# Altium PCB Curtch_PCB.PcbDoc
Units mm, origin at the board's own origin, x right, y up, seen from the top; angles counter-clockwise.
Board outline 152.4 x 101.6 mm, 2 copper layers (Top Layer, Bottom Layer); 8 components, 15 nets, 77 pads, 8 vias.
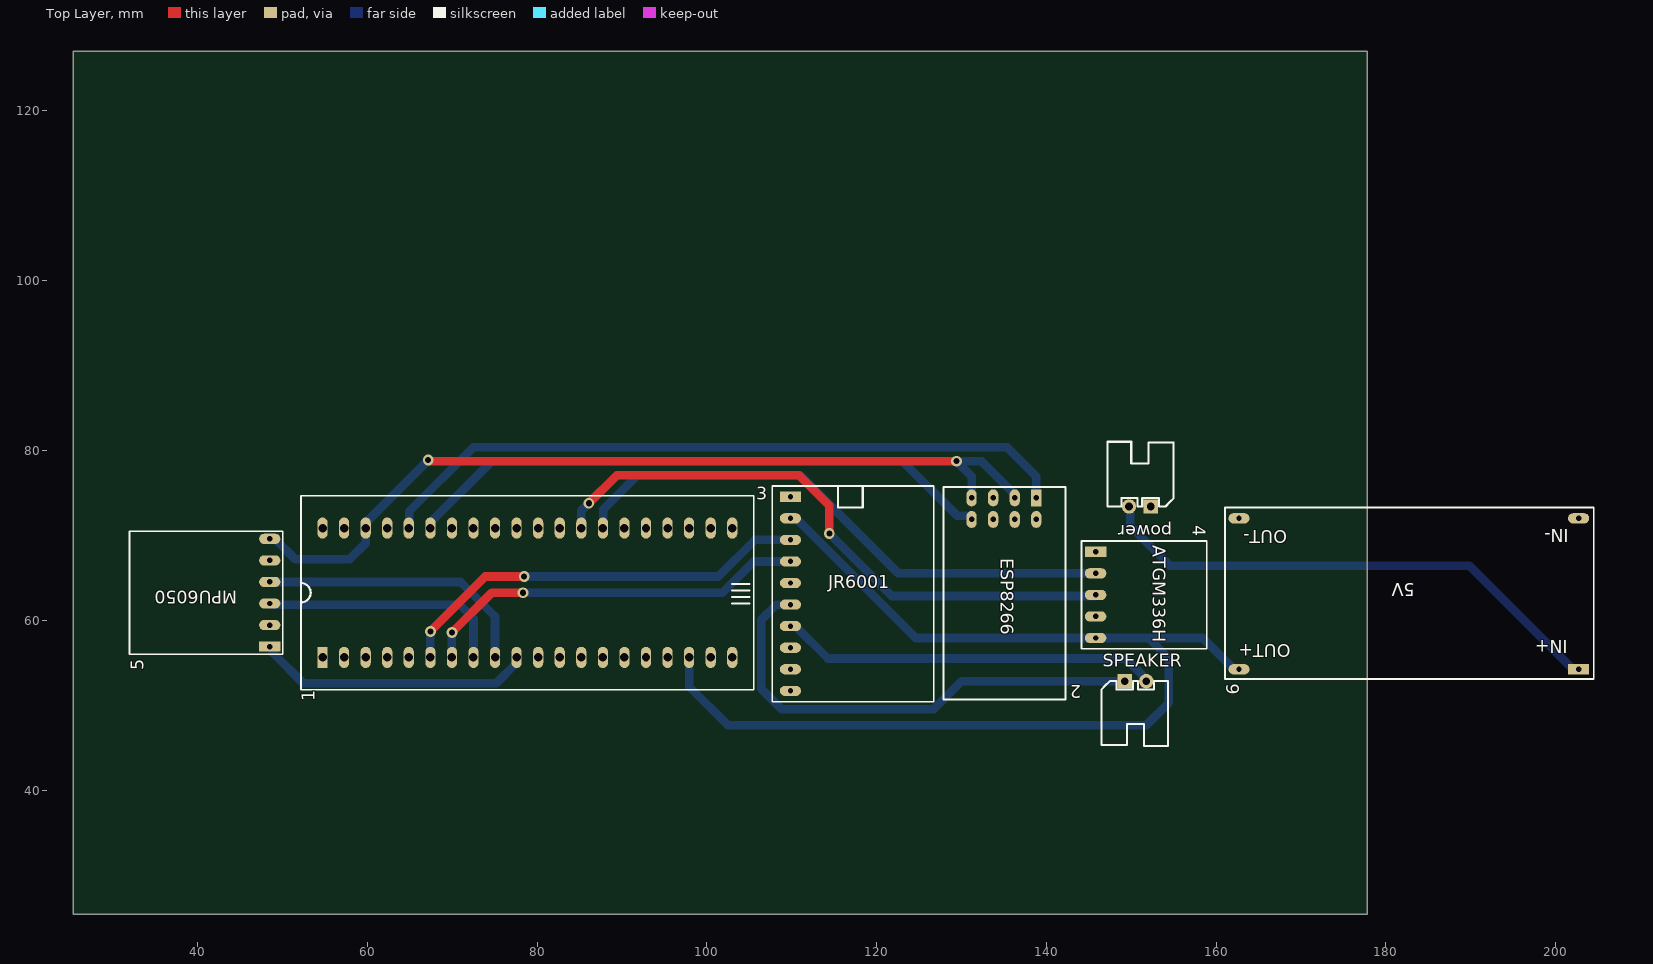
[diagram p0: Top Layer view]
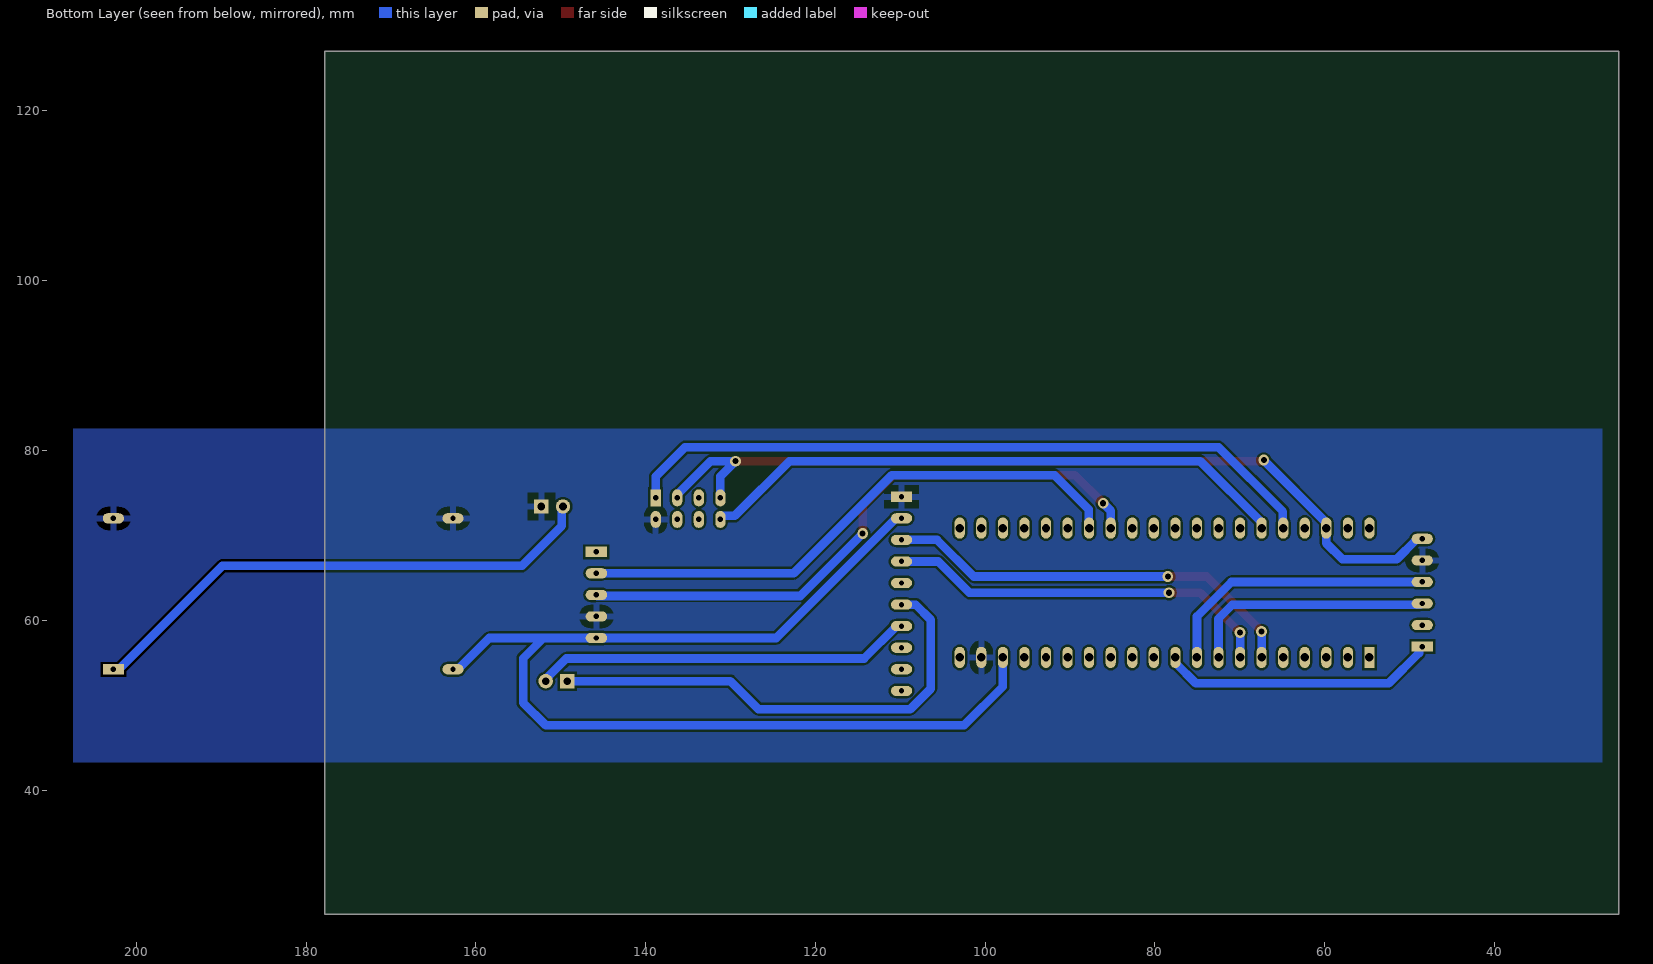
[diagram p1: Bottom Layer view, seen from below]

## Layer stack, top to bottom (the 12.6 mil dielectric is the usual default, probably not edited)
Top Solder: solder mask 0.0102, Solder Resist, Dk 3.5
Top Layer: signal copper 0.0356
Dielectric 1: dielectric 0.32, FR-4, Dk 4.8
Bottom Layer: signal copper 0.0356
Bottom Solder: solder mask 0.0102, Solder Resist, Dk 3.5

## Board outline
25.4,25.4 177.8,25.4 177.8,127 25.4,127

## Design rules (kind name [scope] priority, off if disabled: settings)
Clearance [All] p1: gap=0.254 ignorepadtopadclearanceinfootprint=FALSE except(0: Arc-Hole Track-Hole SMDPad-Hole THPad-Hole Via-Hole Fill-Hole Poly-Hole Region-Hole Text-Hole)
PlaneClearance [InNet('GND')] p1: clearance=0.508
PlaneConnect PlaneConnect_1 [All] p1: planeconnectstyle=Relief reliefexpansion=0.508 reliefentries=4 reliefconductorwidth=0.254 reliefairgap=0.254
PolygonConnect [InNet('GND') vs InNet('GND')] p1: connectstyle=Relief reliefconductorwidth=0.762 reliefentries=4 polygonreliefangle="90 Angle" airgapwidth=0.762
RoutingVias [All] p1: holewidth=0.711 width=1.27 viastyle="Through Hole" minholewidth=0.711 minwidth=1.27 maxholewidth=0.711 maxwidth=1.27
SolderMaskExpansion [All] p1: expansion=0.102 istentingtop=FALSE
Width [All] p1: maxlimit=1.016 minlimit=0.762 preferedwidth=1.016
28 further rules are at their usual default settings.

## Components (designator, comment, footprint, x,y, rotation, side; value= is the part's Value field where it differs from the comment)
1 "STM32最小系统板" DIP40 54.737,55.626 r90 top
2 "ESP8266" "DIP8 - duplicate" 138.811,74.422 r270 top
3 "JR6001" DIP20 109.855,74.549 r0 top
4 "ATGM336H" DIP10 145.796,68.072 r0 top
5 "MPU6050" MPU6050 48.514,56.896 r180 top
6 "5V稳压" DIP16 202.687,54.229 r180 top
power "HDR-1X2" XH2.54-WI-2P 151.003,73.406 r180 top
SPEAKER "HDR-1X2" XH2.54-WI-2P 150.495,52.832 r0 top

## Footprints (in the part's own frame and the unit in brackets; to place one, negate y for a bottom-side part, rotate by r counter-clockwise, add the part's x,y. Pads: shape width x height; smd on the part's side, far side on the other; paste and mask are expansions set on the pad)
"DIP8 - duplicate" [mm]
  rect 2x1.2 hole 0.64: 1(0,0)
  oval 2x1.2 hole 0.64: 2(0,-2.54) 3(0,-5.08) 4(0,-7.62) 5(2.54,-7.62) 6(2.54,-5.08) 7(2.54,-2.54) 8(2.54,0)
  silkscreen extent -1.27,-10.92 23.75,3.43
DIP10 [mm]
  rect 2.54x1.2 / inner rect 2.5x1.2 / far side rect 2.54x1.2 hole 0.64: 1(0,0)
  oval 2.54x1.2 / inner oval 2.5x1.2 / far side oval 2.54x1.2 hole 0.64: 2(0,-2.54) 3(0,-5.08) 4(0,-7.62) 5(0,-10.16)
  silkscreen extent -1.65,-11.43 13.1,1.27
DIP16 [mm]
  rect 2.5x1.2 hole 0.64: 1(0,0)
  oval 2.5x1.2 hole 0.64: 2(0,-17.78) 3(40,-17.78) 4(40,0)
  silkscreen extent -1.78,-19.05 41.66,1.14
DIP20 [mm]
  rect 2.5x1.2 hole 0.64: 1(0,0)
  oval 2.5x1.2 hole 0.64: 2(0,-2.54) 3(0,-5.08) 4(0,-7.62) 5(0,-10.16) 6(0,-12.7) 7(0,-15.24) 8(0,-17.78) 9(0,-20.32) 10(0,-22.86)
  silkscreen extent -2.16,-24.13 16.89,1.27
DIP40 [mm]
  rect 2.5x1.2 hole 1: 1(0,0)
  oval 2.5x1.2 hole 1: 2(0,-2.54) 3(0,-5.08) 4(0,-7.62) 5(0,-10.16) 6(0,-12.7) 7(0,-15.24) 8(0,-17.78) 9(0,-20.32) 10(0,-22.86) 11(0,-25.4) 12(0,-27.94) 13(0,-30.48) 14(0,-33.02) 15(0,-35.56) 16(0,-38.1) 17(0,-40.64) 18(0,-43.18) 19(0,-45.72) 20(0,-48.26) 21(15.24,-48.26) 22(15.24,-45.72) 23(15.24,-43.18) 24(15.24,-40.64) 25(15.24,-38.1) 26(15.24,-35.56) 27(15.24,-33.02) 28(15.24,-30.48) 29(15.24,-27.94) 30(15.24,-25.4) 31(15.24,-22.86) 32(15.24,-20.32) 33(15.24,-17.78) 34(15.24,-15.24) 35(15.24,-12.7) 36(15.24,-10.16) 37(15.24,-7.62) 38(15.24,-5.08) 39(15.24,-2.54) 40(15.24,0)
  silkscreen extent -3.81,-50.8 19.05,2.54
MPU6050 [mm]
  rect 2.5x1.2 hole 0.64: 1(0,0)
  oval 2.5x1.2 hole 0.64: 2(0,-2.54) 3(0,-5.08) 4(0,-7.62) 5(0,-10.16) 6(0,-12.7)
  silkscreen extent -1.52,-13.59 16.51,0.89
XH2.54-WI-2P [mm] "接插件，2P"
  rect 1.7x1.7 hole 0.9: 1(-1.27,0)
  round 1.7 hole 0.9: 2(1.27,0)
  silkscreen extent -3.99,-7.62 3.81,0, body extent -3.77,-7.35 3.77,0.35, height 5.73

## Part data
2: library part Component_1
power SPEAKER: library part "Header 2", "2P接插件"

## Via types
v1: diameter 1.27, hole 0.711, Top Layer to Bottom Layer, 8 vias

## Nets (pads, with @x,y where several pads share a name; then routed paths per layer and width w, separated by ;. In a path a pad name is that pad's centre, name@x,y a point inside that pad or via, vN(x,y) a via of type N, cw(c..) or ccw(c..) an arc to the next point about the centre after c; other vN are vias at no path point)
3.3V: 1.38 2.2 2.4 5.6 | length 102
  Top Layer w1.016: v1(67.183,78.867) 67.252,78.867 67.379,78.74 v1(129.413,78.74)
  Bottom Layer w1.016: 5.6 49.114,69.596 49.256,69.454 49.256,69.449 51.522,67.183 57.912,67.183 59.817,69.088 1.38 59.817,71.501 v1@67.056,78.74 ; 2.4 131.191,76.962 v1(129.413,78.74) 132.353,78.74 136.271,74.822 2.2
5V: 1.18 3.2 4.5 6.4 | length 131.9
  Top Layer w1.016: 3.2 3.2@109.982,71.882
  Bottom Layer w1.016: 1.18 97.917,52.197 102.489,47.625 151.765,47.625 154.432,50.292 154.432,55.499 152.019,57.912 ; 3.2 110.505,72.009 124.602,57.912 4.5 152.019,57.912 ; 6.4 162.087,54.229 158.404,57.912 152.019,57.912
8V: 6.1 power.2 | length 62.2
  Bottom Layer w1.016: power.2 149.864,73.275 149.864,71.116 154.559,66.421 189.845,66.421 202.037,54.229 6.1
GND: 1.19 2.8 3.1 4.4 5.5 6.2 6.3 power.1
PA2: 1.27 4.2 | length 66.7
  Bottom Layer w1.016: 1.27 87.792,70.901 87.792,73.06 91.821,77.089 110.998,77.089 122.555,65.532 4.2
PA3: 1.28 4.3 | length 72.2
  Top Layer w1.016: v1(86.106,73.787) 89.408,77.089 110.871,77.089 114.427,73.533 v1(114.427,70.231)
  Bottom Layer w1.016: 1.28 85.217,72.898 v1(86.106,73.787) ; v1(114.427,70.231) 121.793,62.865 145.669,62.865 4.3
PA9: 1.6 3.3 | length 49.9
  Top Layer w1.016: v1(67.437,58.674) 73.914,65.151 v1(78.486,65.151)
  Bottom Layer w1.016: 1.6 v1(67.437,58.674) ; v1(78.486,65.151) 101.346,65.151 105.664,69.469 3.3
PA10: 1.7 3.4 | length 46.3
  Top Layer w1.016: v1(69.977,58.547) 74.676,63.246 v1(78.333,63.246)
  Bottom Layer w1.016: 1.7 v1(69.977,58.547) ; v1(78.333,63.246) 101.854,63.246 105.537,66.929 3.4
PA11: 1.8 5.3 | length 29.3
  Bottom Layer w1.016: 5.3 48.641,61.976 48.768,61.849 70.866,61.849 72.517,60.198 1.8
PA12: 1.9 5.4 | length 33.1
  Bottom Layer w1.016: 5.4 70.993,64.516 75.057,60.452 1.9
PA15: 1.10 5.1 | length 32.9
  Bottom Layer w1.016: 5.1 48.803,56.896 48.895,56.804 48.895,56.134 52.451,52.578 75.199,52.578 77.597,54.976 1.10
PB10: 1.36 2.1 | length 82.9
  Bottom Layer w1.016: 1.36 64.932,70.901 64.932,72.806 72.517,80.391 135.366,80.391 138.811,76.946 2.1
PB11: 1.35 2.5 | length 70.4
  Bottom Layer w1.016: 1.35 67.437,71.516 74.661,78.74 123.063,78.74 129.486,72.317 131.106,72.317 131.191,72.232 2.5
SPK+: 3.6 SPEAKER.1 | length 57.5
  Bottom Layer w1.016: 3.6 108.204,61.849 106.426,60.071 106.426,51.943 108.839,49.53 126.712,49.53 130.014,52.832 SPEAKER.1
SPK-: 3.7 SPEAKER.2 | length 44.7
  Bottom Layer w1.016: 3.7 110.455,59.309 114.265,55.499 149.336,55.499 151.634,53.201 151.634,52.963 SPEAKER.2
pads on no net: 1.1 1.2 1.3 1.4 1.5 1.11 1.12 1.13 1.14 1.15 1.16 1.17 1.20 1.21 1.22 1.23 1.24 1.25 1.26 1.29 1.30 1.31 1.32 1.33 1.34 1.37 1.39 1.40 2.3 2.6 2.7 3.5 3.8 3.9 3.10 4.1 5.2

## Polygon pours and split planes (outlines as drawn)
GND on Bottom Layer "GND_L02_P000" (solid, remove dead copper, pour order 0): 27.305,43.307 27.305,82.55 207.391,82.55 207.391,43.307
